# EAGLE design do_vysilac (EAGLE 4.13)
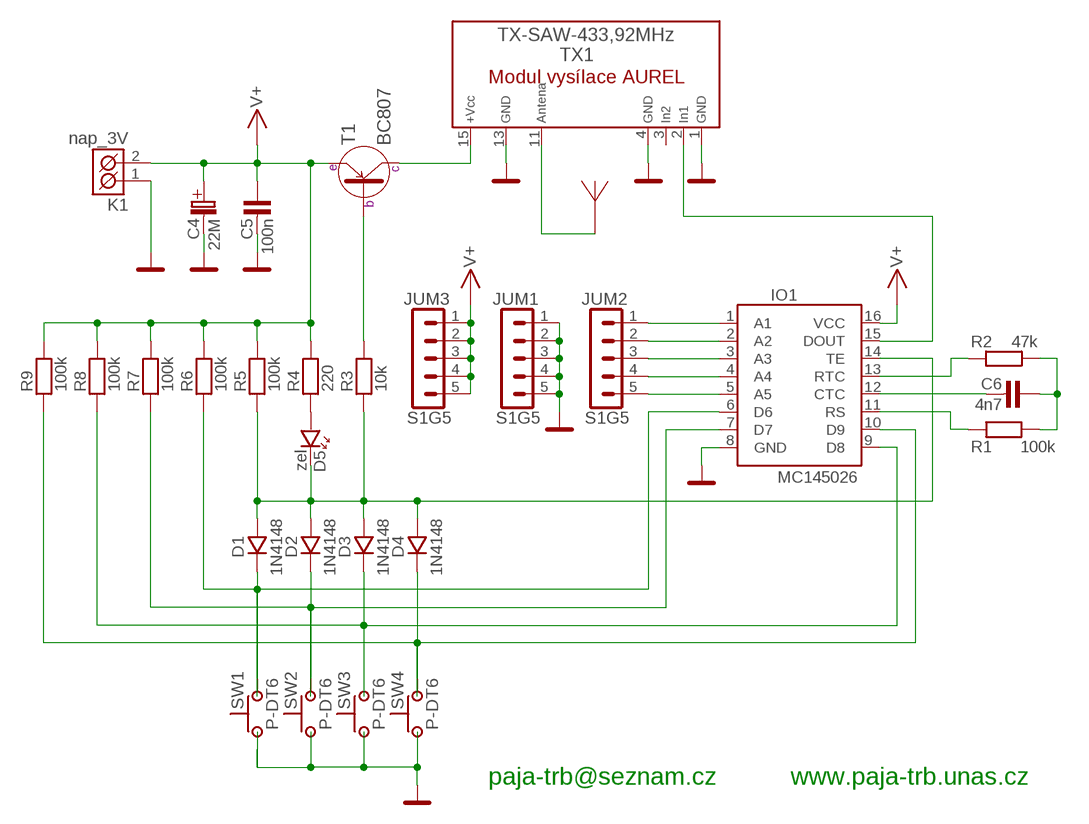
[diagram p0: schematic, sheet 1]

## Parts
ANT1  ANTENA  [PAD_1]
C4  22M  C-ELEKTROLYT_2  [C-EL_2]
C5  100n  C-KERAMIK_SMD_1206  [1206]
C6  4n7  C-KERAMIK_SMD_1206  [1206]
D1  1N4148  1N4148_SMD_SOD80  [SOD-80]
D2  1N4148  1N4148_SMD_SOD80  [SOD-80]
D3  1N4148  1N4148_SMD_SOD80  [SOD-80]
D4  1N4148  1N4148_SMD_SOD80  [SOD-80]
D5  zel  LED_3  [LED_3]
IO1  MC145026  [DIL16]
JUM1  S1G5  S1G5_JUMP  [S1G5_JUM]
JUM2  S1G5  S1G5_JUMP  [S1G5_JUM]
JUM3  S1G5  S1G5_JUMP  [S1G5_JUM]
K1  nap_3V  CZM_5/2  [CZM_5/2]
R1  100k  R_SMD_1206  [1206]
R2  47k  R_SMD_1206  [1206]
R3  10k  R_SMD_1206  [1206]
R4  220  R_SMD_1206  [1206]
R5  100k  R_SMD_1206  [1206]
R6  100k  R_SMD_1206  [1206]
R7  100k  R_SMD_1206  [1206]
R8  100k  R_SMD_1206  [1206]
R9  100k  R_SMD_1206  [1206]
SW1  P-DT6  P-DT6_KULATY_KULATY  [P-DT6]
SW2  P-DT6  P-DT6_KULATY_KULATY  [P-DT6]
SW3  P-DT6  P-DT6_KULATY_KULATY  [P-DT6]
SW4  P-DT6  P-DT6_KULATY_KULATY  [P-DT6]
T1  BC807  [SOT-23]
TX1  TX-SAW433  [TX-SAW]

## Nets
+3V: C4.C+(C_EL+) C5.1 IO1.16(VCC) JUM3.1 JUM3.2 JUM3.3 JUM3.4 JUM3.5 K1.2(K2) R4.2 R5.2 R6.2 R7.2 R8.2 R9.2 T1.1(E) ; supply symbol labelled V+
GND: C4.C-(C_EL-) C5.2 IO1.8(GND) JUM1.1 JUM1.2 JUM1.3 JUM1.4 JUM1.5 K1.1(K1) SW1.1 SW1.1A SW2.1 SW2.1A SW3.1 SW3.1A SW4.1 SW4.1A TX1.1(GND) TX1.4(GND) TX1.13(GND)
N$1: IO1.11(RS) R1.1
N$3: D2.K IO1.7(D7) R7.1 SW2.2 SW2.2A
N$4: D5.A R4.1
N$5: IO1.1(A1) JUM2.1
N$6: D1.K IO1.6(D6) R6.1 SW1.2 SW1.2A
N$7: D1.A D2.A D3.A D4.A D5.K IO1.14(TE) R3.1 R5.1
N$8: IO1.15(DOUT) TX1.2(IN1)
N$9: IO1.13(RTC) R2.1
N$10: C6.2 IO1.12(CTC)
N$11: C6.1 R1.2 R2.2
N$12: D4.K IO1.10(D9) R9.1 SW4.2 SW4.2A
N$13: D3.K IO1.9(D8) R8.1 SW3.2A
N$14: R3.2 T1.2(B)
N$15: T1.3(C) TX1.15(VCC)
N$21: IO1.2(A2) JUM2.2
N$22: IO1.3(A3) JUM2.3
N$23: IO1.4(A4) JUM2.4
N$24: IO1.5(A5) JUM2.5
N$25: ANT1.1 TX1.11(ANTENA)
Unconnected: SW3.2 TX1.3(IN2)

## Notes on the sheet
- paja-trb@seznam.cz | www.paja-trb.unas.cz

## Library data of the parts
ANT1 = #PaJa_15:ANTENA: SCH symbol - Anteny + pajeci bod na DPS
C4 = #PaJa_15:C-ELEKTROLYT: Kondenzator - elektrolyticky
C5 C6 = #PaJa_15:C-KERAMIK: Kondenzator - keramicky
D1-D4 = #PaJa_15:1N4148: Univerzalni dioda - 0,15A, 75V
D5 = #PaJa_15:LED: LED - jednobarevna
IO1 = #PaJa_15:MC145026
JUM1-JUM3 = #PaJa_15:S1G5_JUMP: Radove konektory - koliky - 5x
K1 = #PaJa_15:CZM_5/2: Svorkovnice - roztec 5,08mm - dvojita
R1-R9 = #PaJa_15:R: Rezistor
SW1-SW4 = #PaJa_15:P-DT6??: Tlacitkovy spinac
T1 = #PaJa_15:BC807
TX1 = #PaJa_15:TX-SAW433

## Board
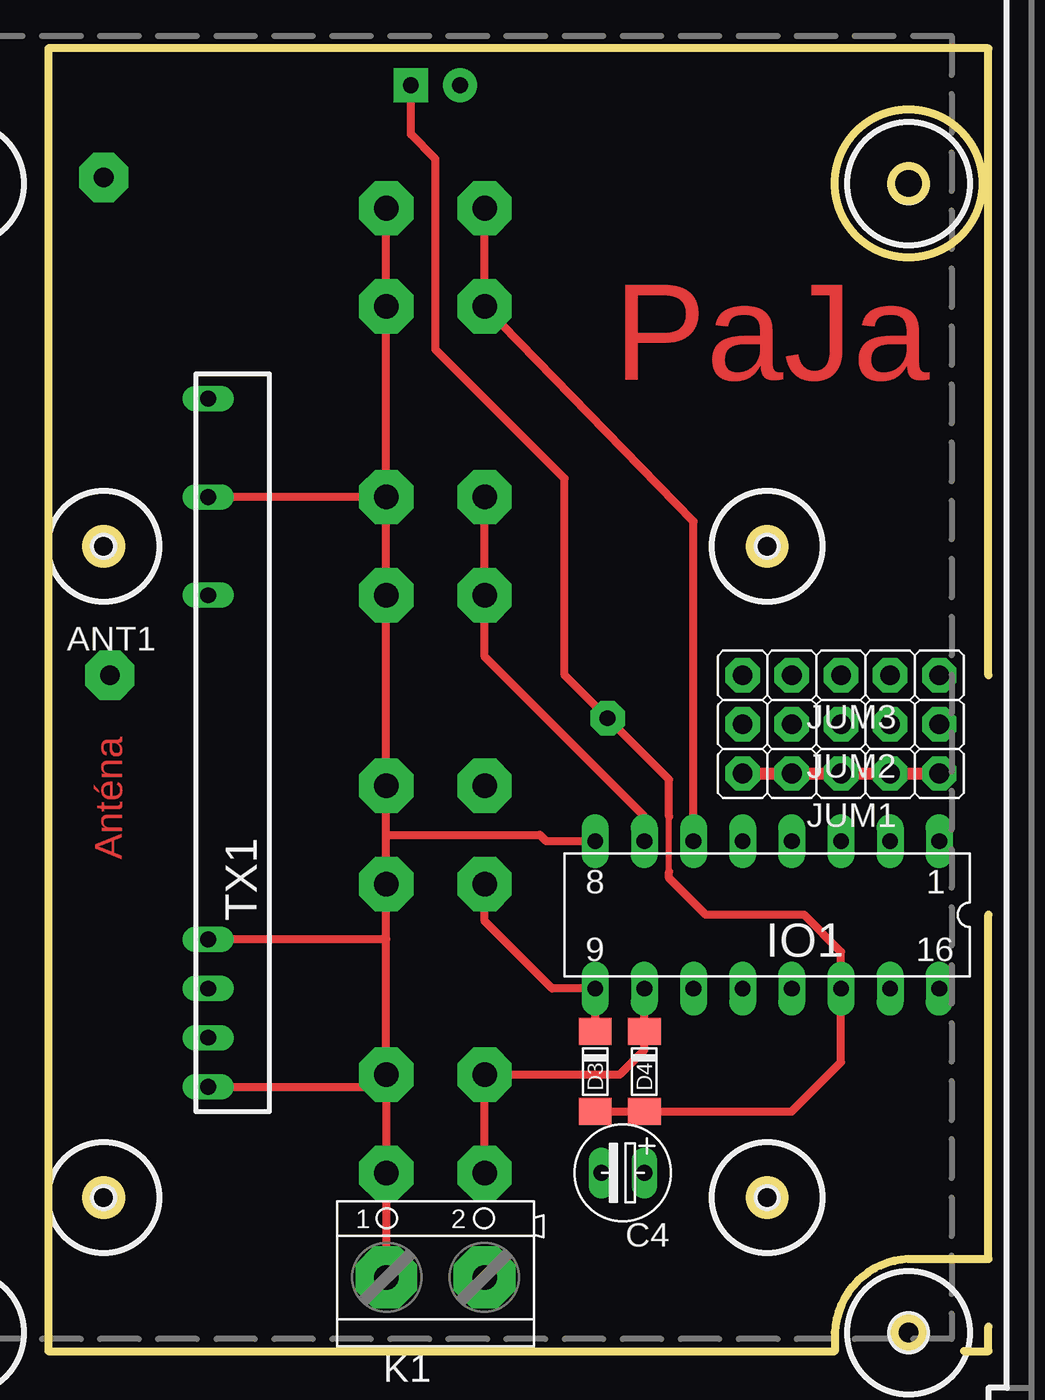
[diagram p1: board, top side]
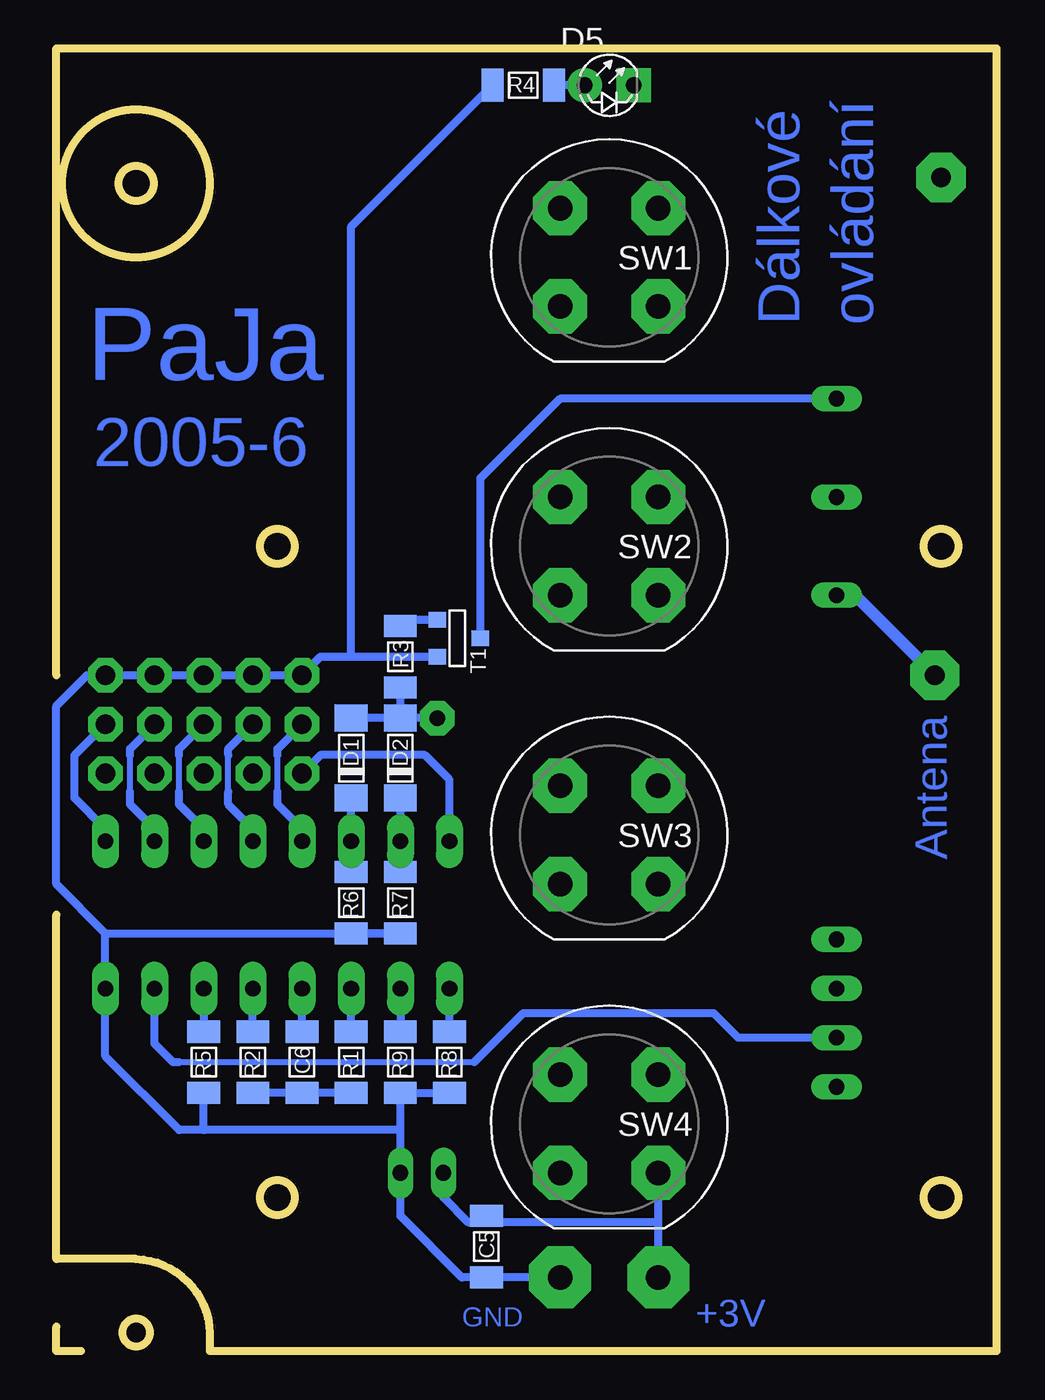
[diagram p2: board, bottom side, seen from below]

Size 48.58 x 67.31 mm. Coordinates in mm from the lower left corner, seen from the top.
Outline: 48.58,34.92 48.58,67.31 0,67.31 0,0 40.64,0 40.64,0.95 arc-85 44.45,4.76 48.58,4.76 48.58,22.54
Outline: 47.31,0 48.58,0 48.58,1.27
Outline: circle at 2.86,7.94 radius 0.9
Outline: circle at 2.86,41.59 radius 0.9
Outline: circle at 37.15,41.59 radius 0.9
Outline: circle at 37.15,7.94 radius 0.9
Outline: circle at 44.45,0.95 radius 0.71
Outline: circle at 44.45,60.32 radius 3.81
Outline: circle at 44.45,60.32 radius 0.9
Copper layers (1*16): Top 0.035mm / dielectric 1.5mm / Bottom 0.035mm
Design rules "default": minimum track width 10mil, minimum drill 24mil, track to track 8mil, track to pad 8mil, pad to pad 8mil, via to via 8mil, smd to smd 8mil, copper to edge 40mil, drill to drill 8mil, minimum pad ring 10mil, minimum via ring 8mil, stop-mask expansion 4mil, vias tented up to drill 0mil, thermal gap 10mil

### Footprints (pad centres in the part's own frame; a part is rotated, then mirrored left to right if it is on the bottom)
PAD_1 = drill 1.016 pad 2.54 octagon: 1 0,0
C-EL_2 = drill 0.813 pad 1.27 long: C+ 0,0; C- 2.223,0
1206 = smd 1.143 x 1.702: 1 -1.587,0; 2 1.587,0
SOD-80 = smd 1.397 x 1.702: A 1.905,0; K -2.223,0
LED_3 = drill 0.813 pad 1.778 round: A -1.27,0 | drill 0.813 pad 1.778 square: K 1.27,0
DIL16 = drill 0.813 pad 1.4 long: 1 -8.89,-3.81; 2 -6.35,-3.81; 3 -3.81,-3.81; 4 -1.27,-3.81; 5 1.27,-3.81; 6 3.81,-3.81; 7 6.35,-3.81; 8 8.89,-3.81; 9 8.89,3.81; 10 6.35,3.81; 11 3.81,3.81; 12 1.27,3.81; 13 -1.27,3.81; 14 -3.81,3.81; 15 -6.35,3.81; 16 -8.89,3.81
S1G5_JUM = drill 1.016 pad 1.778 octagon: 1 -5.08,0; 2 -2.54,0; 3 0,0; 4 2.54,0; 5 5.08,0
CZM_5/2 = drill 1.27 pad 3.2 octagon: 1 -2.54,0; 2 2.54,0
P-DT6 = drill 1.27 pad 2.8 octagon: 1 -2.54,-2.54; 1A -2.54,2.54; 2 2.54,-2.54; 2A 2.54,2.54
SOT-23 = smd 0.787 x 0.889: 1 0.953,-0.953; 2 -0.953,-0.953; 3 0,1.27
TX-SAW = drill 0.813 pad 1.27 long: 1 -17.78,0.318; 2 -15.24,0.318; 3 -12.7,0.318; 4 -10.16,0.318; 11 7.62,0.318; 13 12.7,0.318; 15 17.78,0.318

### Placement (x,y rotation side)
ANT1  3.18,34.92 0 top
C4  30.8,9.21 180 top
C5  26.35,5.4 90 bottom
C6  35.88,14.92 90 bottom
D1  33.34,30.8 90 bottom
D2  30.8,30.8 90 bottom
D3  28.26,14.29 270 top
D4  30.8,14.29 270 top
D5  20,65.41 0 bottom
IO1  37.15,22.54 180 top
JUM1  40.96,29.84 180 top
JUM2  40.96,32.38 180 top
JUM3  40.96,34.92 180 top
K1  20,3.81 0 top
R1  33.34,14.92 270 bottom
R2  38.42,14.92 270 bottom
R3  30.8,35.88 90 bottom
R4  24.45,65.41 180 bottom
R5  40.96,14.92 270 bottom
R6  33.34,23.18 270 bottom
R7  30.8,23.18 270 bottom
R8  28.26,14.92 270 bottom
R9  30.8,14.92 270 bottom
SW1  20,56.52 180 bottom
SW2  20,41.59 180 bottom
SW3  20,26.67 180 bottom
SW4  20,11.75 180 bottom
T1  27.94,36.83 270 bottom
TX1  8.57,31.43 90 top
U$1  [U-KP20]  not placed on the board

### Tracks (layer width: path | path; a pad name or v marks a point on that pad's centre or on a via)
+3V
  Bottom 0.406: JUM3.1 JUM3.2 JUM3.3 | JUM3.3 JUM3.4 JUM3.5 34.92,35.88 33.34,35.88 | JUM3.1 JUM3.3 | 33.34,35.88 T1.1 | 33.34,35.88 33.34,58.1 R4.2 | 46.04,21.59 IO1.16 46.04,15.24 42.23,11.43 40.96,11.43 | 46.04,21.59 48.58,24.13 48.58,33.34 46.99,34.92 JUM3.1 | R6.2 R7.2 46.04,21.59 | 30.8,11.43 R9.2 R8.2 | 30.8,11.43 40.96,11.43 | 40.96,11.43 R5.2 | K1.2 C5.1 27.62,3.81 30.8,6.98 C4.C+ 30.8,11.43
GND
  Top 0.406: SW2.1 SW1.1A | SW1.1A SW1.1 SW1.1A | SW2.1A SW3.1 17.46,26.67 | SW2.1A SW2.1 | 17.46,21.27 SW4.1 17.46,13.65 | 17.46,21.27 SW3.1A 17.46,26.67 | SW2.1A SW2.1 | 17.46,13.65 SW4.1A K1.1 | SW2.1 TX1.13 | 17.46,21.27 TX1.4 | TX1.1 17.46,13.65 | 17.46,26.67 25.4,26.67 25.72,26.35 IO1.8
  Top 0.61: JUM1.5 JUM1.4 JUM1.3 JUM1.2 JUM1.1
  Bottom 0.406: JUM1.5 34.92,30.8 29.53,30.8 28.26,29.53 IO1.8 | K1.1 17.46,6.67 | 17.46,6.67 26.35,6.67 | C4.C- 28.57,7.94 27.3,6.67 26.35,6.67 | 26.35,6.67 C5.2 | 17.46,6.67 SW4.1A
N$1
  Bottom 0.406: R1.1 IO1.11
N$3
  Top 0.406: IO1.7 30.8,27.62 22.54,35.88 SW2.2A SW2.2
  Bottom 0.406: R7.1 IO1.7 D2.K
N$4
  Bottom 0.406: D5.A R4.1
N$5
  Bottom 0.406: JUM2.1 47.62,30.8 47.62,28.58 46.04,26.99 IO1.1
N$6
  Top 0.406: SW1.2 SW1.2A 33.34,42.86 IO1.6
  Bottom 0.406: R6.1 IO1.6 D1.K
N$7  (via drill 0.81 pad 1.78)
  Top 0.305: 32.07,24.76 32.07,27.62
  Top 0.406: D3.A D4.A 38.42,12.38 40.96,14.92 IO1.14 40.96,20.64 39.05,22.54 33.97,22.54 32.07,24.45 32.07,24.76 | 32.07,27.62 32.07,29.53 v28.89,32.7 26.67,34.92 26.67,45.09 20,51.75 20,61.6 18.73,62.86 D5.K
  Bottom 0.406: IO1.14 R5.1 | D2.A D1.A | v28.89,32.7 D2.A | D2.A R3.1
N$8
  Bottom 0.305: 26.99,14.92 42.23,14.92
  Bottom 0.406: TX1.2 13.33,16.19 14.6,17.46 24.45,17.46 26.99,14.92 | IO1.15 43.5,15.88 42.55,14.92 42.23,14.92
N$9
  Bottom 0.406: R2.1 IO1.13
N$10
  Bottom 0.406: C6.2 IO1.12
N$11
  Bottom 0.406: R2.2 C6.1 R1.2
N$12
  Top 0.406: SW4.2A SW4.2 29.53,14.29 30.8,15.56 R9.1 IO1.10
  Bottom 0.406: IO1.10 R9.1
N$13
  Top 0.406: R8.1 IO1.9 26.03,18.73 22.54,22.22 SW3.2A
  Bottom 0.406: R8.1 IO1.9
N$14
  Bottom 0.406: T1.2 30.48,37.78 R3.2
N$15
  Bottom 0.406: TX1.15 22.54,49.21 26.67,45.09 T1.3
N$16  (via drill 1.02 pad 2.54)
  other vias: 2.86,60.64
N$21
  Bottom 0.305: 44.77,28.89 44.77,30.8
  Bottom 0.406: IO1.2 43.5,26.99 44.77,28.26 44.77,28.89 | JUM2.2 44.77,31.11 44.77,30.8
N$22
  Bottom 0.305: 42.23,28.89 42.23,30.8
  Bottom 0.406: IO1.3 40.96,26.99 42.23,28.26 42.23,28.89 | JUM2.3 42.23,31.11 42.23,30.8
N$23
  Bottom 0.305: 39.69,28.89 39.69,30.8
  Bottom 0.406: IO1.4 38.42,26.99 39.69,28.26 39.69,28.89 | JUM2.4 39.69,31.11 39.69,30.8
N$24
  Bottom 0.305: 37.15,28.89 37.15,30.8
  Bottom 0.406: IO1.5 35.88,26.99 37.15,28.26 37.15,28.89 | JUM2.5 37.15,31.11 37.15,30.8
N$25
  Bottom 0.61: TX1.11 7.3,39.05 ANT1.1

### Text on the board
Top: PaJa | Anténa
Bottom: ovládání | Dálkové | PaJa | 2005-6 | Antena | +3V | GND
